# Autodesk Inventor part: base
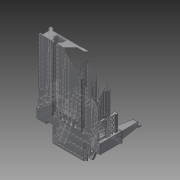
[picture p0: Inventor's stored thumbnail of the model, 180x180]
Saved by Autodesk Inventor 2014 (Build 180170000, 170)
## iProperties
Created: 2013-07
Part Number: base
Material: Generic
Document SubType Name: Modeling
Designer: Brent J. Rosenburgh
Density: 1 g/cm^3
Appearance: Default
Author: Brent J. Rosenburgh
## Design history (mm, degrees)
sketch "Sketch1"
  geometry: L1 (-56, -78)-(56, -78); L2 (56, -78)-(56, -100); L3 (56, -100)-(-56, -100); L4 (-56, -100)-(-56, -78); 1 further point
  constraints: 8 end point, 2 parallel, 1 horizontal, 1 perpendicular
extrude "Extrusion1" new body sketch "Sketch1" distance "d0" = 136; taper "d1" = 0 deg
sketch "Sketch2"
  geometry: L1 (0, 136)-(12, 136); L2 (12, 136)-(12, 124); L3 (12, 124)-(0, 124); L4 (0, 124)-(0, 136); L5 (112, 136)-(100, 136); L6 (100, 136)-(100, 124); L7 (100, 124)-(112, 124); L8 (112, 124)-(112, 136); 1 further point
  constraints: 16 end point, 4 parallel, 2 horizontal, 2 perpendicular
extrude "Extrusion2" join sketch "Sketch2" distance "d2" = 16; taper "d3" = 0 deg
sketch "Sketch3"
  geometry: L1 (0, 136)-(0, 124) reference; L2 (0, 124)-(12, 124) reference; L3 (12, 124)-(12, 136) reference; L4 (12, 136)-(0, 136) reference; L5 (15, 121)-(-3, 121); L6 (-3, 121)-(-3, 139); L7 (-3, 139)-(15, 139); L8 (15, 139)-(15, 121); 1 further point
  constraints: 8 end point, 2 parallel, 1 horizontal, 1 perpendicular
extrude "Extrusion3" join sketch "Sketch3" distance "d4" = 38; taper "d5" = 0 deg
sketch "Sketch4"
  geometry: L1 (112, 136)-(100, 136) reference; L2 (100, 136)-(100, 124) reference; L3 (100, 124)-(112, 124) reference; L4 (112, 124)-(112, 136) reference; L5 (115, 121)-(97, 121); L6 (97, 121)-(97, 139); L7 (97, 139)-(115, 139); L8 (115, 139)-(115, 121); 1 further point
  constraints: 8 end point, 2 parallel, 1 horizontal, 1 perpendicular
extrude "Extrusion4" join sketch "Sketch4" distance "d6" = 38; taper "d7" = 0 deg
sketch "Sketch5"
  geometry: L1 (15, 121)-(-3, 121) reference; L2 (15, 139)-(15, 121) reference; L3 (-3, 139)-(15, 139) reference; L4 (-3, 121)-(-3, 139) reference; 1 further point
extrude "Extrusion5" join sketch "Sketch5" distance "d8" = 1; taper "d9" = 45 deg
sketch "Sketch6"
  geometry: L1 (-4, 120)-(-4, 140) reference; L2 (16, 120)-(-4, 120) reference; L3 (16, 140)-(16, 120) reference; L4 (-4, 140)-(16, 140) reference; 1 further point
extrude "Extrusion6" join sketch "Sketch6" distance "d10" = 1; taper "d11" = 0 deg
sketch "Sketch7"
  geometry: L1 (-4, 140)-(-4, 120) reference; L2 (-4, 120)-(16, 120) reference; L3 (16, 120)-(16, 140) reference; L4 (16, 140)-(-4, 140) reference; 1 further point
extrude "Extrusion7" join sketch "Sketch7" distance "d12" = 1; taper "d13" = -45 deg
sketch "Sketch8"
  geometry: L1 (115, 121)-(97, 121) reference; L2 (115, 139)-(115, 121) reference; L3 (97, 139)-(115, 139) reference; L4 (97, 121)-(97, 139) reference; 1 further point
extrude "Extrusion8" join sketch "Sketch8" distance "d14" = 1; taper "d15" = 45 deg
sketch "Sketch9"
  geometry: L1 (96, 120)-(96, 140) reference; L2 (116, 120)-(96, 120) reference; L3 (116, 140)-(116, 120) reference; L4 (96, 140)-(116, 140) reference; 1 further point
extrude "Extrusion9" join sketch "Sketch9" distance "d16" = 1; taper "d17" = 0 deg
sketch "Sketch10"
  geometry: L1 (96, 140)-(96, 120) reference; L2 (96, 120)-(116, 120) reference; L3 (116, 120)-(116, 140) reference; L4 (116, 140)-(96, 140) reference; 1 further point
extrude "Extrusion10" join sketch "Sketch10" distance "d18" = 1; taper "d19" = -45 deg
sketch "Sketch11"
  geometry: L1 (113, 137)-(99, 137); L2 (99, 137)-(99, 123); L3 (99, 123)-(113, 123); L4 (113, 123)-(113, 137); L5 (113, 137)-(99, 123); L6 (99, 137)-(113, 123); 2 further points
  constraints: 12 end point, 2 midpoint, 2 parallel, 1 horizontal, 1 perpendicular
extrude "Extrusion11" join sketch "Sketch11" distance "d20" = 34; taper "d21" = -5 deg
sketch "Sketch12"
  geometry: L1 (-1, 123)-(13, 123); L2 (13, 123)-(13, 137); L3 (13, 137)-(-1, 137); L4 (-1, 137)-(-1, 123); L5 (-1, 123)-(13, 137); L6 (13, 123)-(-1, 137); 2 further points
  constraints: 12 end point, 2 midpoint, 2 parallel, 1 horizontal, 1 perpendicular
extrude "Extrusion12" join sketch "Sketch12" distance "d22" = 34; taper "d23" = -5 deg
sketch "Sketch13"
  geometry: L1 (110.025, 134.025)-(110.025, 125.975) reference; L2 (101.975, 134.025)-(110.025, 134.025) reference; L3 (101.975, 125.975)-(101.975, 134.025) reference; L4 (110.025, 125.975)-(101.975, 125.975) reference; 1 further point
extrude "Extrusion13" join sketch "Sketch13" distance "d24" = 1; taper "d25" = 45 deg
sketch "Sketch14"
  geometry: L1 (1.975, 125.975)-(1.975, 134.025) reference; L2 (10.025, 125.975)-(1.975, 125.975) reference; L3 (10.025, 134.025)-(10.025, 125.975) reference; L4 (1.975, 134.025)-(10.025, 134.025) reference; 1 further point
extrude "Extrusion14" join sketch "Sketch14" distance "d26" = 1; taper "d27" = 45 deg
sketch "Sketch15"
  geometry: L1 (111.025, 124.975)-(100.975, 124.975) reference; L2 (111.025, 135.025)-(111.025, 124.975) reference; L3 (100.975, 135.025)-(111.025, 135.025) reference; L4 (100.975, 124.975)-(100.975, 135.025) reference; 1 further point
extrude "Extrusion15" join sketch "Sketch15" distance "d28" = 4.5; taper "d29" = 0 deg
sketch "Sketch16"
  geometry: L1 (0.975, 135.025)-(11.025, 135.025) reference; L2 (0.975, 124.975)-(0.975, 135.025) reference; L3 (11.025, 124.975)-(0.975, 124.975) reference; L4 (11.025, 135.025)-(11.025, 124.975) reference; 1 further point
extrude "Extrusion16" join sketch "Sketch16" distance "d30" = 4.5; taper "d31" = 0 deg
sketch "Sketch17"
  geometry: L1 (-10.051, 4.5)-(0, 4.5) reference; L2 (-10.051, 0)-(-10.051, 4.5) reference; L3 (-2.826, 4.5)-(-2.826, -0.41); L4 (-2.826, -0.41)-(-6.702, -0.41); L5 (-6.702, -0.41)-(-10.051, -1.07); L6 (-10.051, -1.07)-(-10.051, 0); 1 further point
  constraints: 8 end point, 2 parallel, 1 perpendicular, 1 point on line
extrude "Extrusion17" cut sketch "Sketch17" distance "d32" = 115.75; taper "d33" = 0 deg
sketch "Sketch18"
  geometry: L1 (0, 14)-(5.994, 14); L2 (5.994, 14)-(5.994, 10); L3 (5.994, 10)-(0, 10); L4 (0, 10)-(0, 14); 1 further point
  constraints: 8 end point, 2 parallel, 1 horizontal, 1 perpendicular
extrude "Extrusion18" join sketch "Sketch18" distance "d34" = 29.25; taper "d35" = 0 deg
sketch "Sketch19"
  geometry: L1 (14.949, 13.961)-(8.949, 13.961); L2 (8.949, 13.961)-(8.949, 9.961); L3 (8.949, 9.961)-(14.949, 9.961); L4 (14.949, 9.961)-(14.949, 13.961); 1 further point
  constraints: 8 end point, 2 parallel, 1 horizontal, 1 perpendicular
extrude "Extrusion19" join sketch "Sketch19" distance "d36" = 29.25; taper "d37" = 0 deg
sketch "Sketch20"
  geometry: L1 (0, 29.25)-(6, 29.25) reference; L2 (5, 3)-(1, 3); L3 (1, 3)-(1, 8); L4 (1, 8)-(5, 8); L5 (5, 8)-(5, 3); L6 (5, 11)-(1, 11); L7 (1, 11)-(1, 16); L8 (1, 16)-(5, 16); L9 (5, 16)-(5, 11); L10 (5, 19)-(1, 19); L11 (1, 19)-(1, 24); L12 (1, 24)-(5, 24); L13 (5, 24)-(5, 19); L14 (1, 27)-(5, 27); L15 (5, 27)-(5, 29.25); L16 (5, 29.25)-(1, 29.25); L17 (1, 29.25)-(1, 27); 1 further point
  constraints: 32 end point, 8 parallel, 4 horizontal, 4 perpendicular, 2 point on line
extrude "Extrusion20" join sketch "Sketch20" distance "d38" = 10.25; taper "d39" = 0 deg
sketch "Sketch21"
  geometry: L1 (0, 29.25)-(5.994, 29.25) reference; L2 (5, 3)-(1, 3); L3 (1, 3)-(1, 8); L4 (1, 8)-(5, 8); L5 (5, 8)-(5, 3); L6 (1, 11)-(5, 11); L7 (5, 11)-(5, 16); L8 (5, 16)-(1, 16); L9 (1, 16)-(1, 11); L10 (5, 19)-(1, 19); L11 (1, 19)-(1, 24); L12 (1, 24)-(5, 24); L13 (5, 24)-(5, 19); L14 (1, 27)-(5, 27); L15 (5, 27)-(5, 29.25); L16 (5, 29.25)-(1, 29.25); L17 (1, 29.25)-(1, 27); 1 further point
  constraints: 32 end point, 8 parallel, 4 horizontal, 4 perpendicular, 1 point on line
extrude "Extrusion21" join sketch "Sketch21" distance "d40" = 10.25; taper "d41" = 0 deg
sketch "Sketch22"
  geometry: L1 (5, 5)-(1, 5); L2 (1, 5)-(1, 6); L3 (1, 6)-(5, 6); L4 (5, 6)-(5, 5); 1 further point
  constraints: 8 end point, 2 parallel, 1 horizontal, 1 perpendicular
extrude "Extrusion22" join sketch "Sketch22" distance "d42" = 28; taper "d43" = 0 deg
sketch "Sketch23"
  geometry: L1 (4, 0)-(4, -9.961) reference; L2 (0, 0)-(0, -9.961) reference; L3 (4, -4.981)-(0, -4.981); L4 (0, -4.981)-(0, -4); L5 (0, -4)-(4, -4); L6 (4, -4)-(4, -4.981); 1 further point
  constraints: 8 end point, 2 parallel, 1 horizontal, 1 midpoint, 1 perpendicular, 1 point on line
extrude "Extrusion23" join sketch "Sketch23" distance "d44" = 28; taper "d45" = 0 deg
sketch "Sketch24"
  geometry: L1 (-13, 36)-(0, 36); L2 (0, 36)-(0, 32); L3 (0, 32)-(-13, 32); L4 (-13, 32)-(-13, 36); 1 further point
  constraints: 8 end point, 2 parallel, 1 horizontal, 1 perpendicular
extrude "Extrusion24" join sketch "Sketch24" distance "d46" = 19; taper "d47" = 0 deg
sketch "Sketch25"
  geometry: L1 (13, 36)-(0, 36); L2 (0, 36)-(0, 32); L3 (0, 32)-(13, 32); L4 (13, 32)-(13, 36); 1 further point
  constraints: 8 end point, 2 parallel, 1 horizontal, 1 perpendicular
extrude "Extrusion25" join sketch "Sketch25" distance "d48" = 19; taper "d49" = 0 deg
sketch "Sketch26"
  geometry: L1 (0, 36)-(0, 32) reference; L2 (13, 32)-(13, 36) reference; L3 (0, 36)-(-32, 17); L4 (0, 32)-(-32, 13); L5 (-32, 13)-(-32, 17); 1 further point
  constraints: 6 end point, 2 parallel
extrude "Extrusion26" join sketch "Sketch26" distance "d50" = 9; taper "d51" = 0 deg
sketch "Sketch27"
  geometry: L1 (0, 32)-(0, 36) reference; L2 (0, 36)-(32, 17); L3 (32, 17)-(32, 13); L4 (32, 13)-(0, 32); 1 further point
  constraints: 6 end point, 2 parallel
extrude "Extrusion27" join sketch "Sketch27" distance "d52" = 9; taper "d53" = 0 deg
sketch "Sketch28"
  geometry: L1 (-41, -100)-(41, -100) reference; L2 (29, -100)-(-29, -100); L3 (-29, -100)-(-29, -94.5); L4 (-29, -94.5)-(29, -94.5); L5 (29, -94.5)-(29, -100); 1 further point
  constraints: 8 end point, 2 parallel, 1 horizontal, 1 perpendicular, 1 point on line
  dimensions: "d54" = 5.5 distance of L2.end L3.end
extrude "Extrusion28" join sketch "Sketch28" distance "d55" = 28; taper "d56" = 0 deg
sketch "Sketch29"
  geometry: L1 (29, -94.5)-(-29, -94.5); L2 (-29, -94.5)-(-29, -89); L3 (-29, -89)-(29, -89); L4 (29, -89)-(29, -94.5); 1 further point
  constraints: 8 end point, 2 parallel, 1 horizontal, 1 perpendicular
extrude "Extrusion29" join sketch "Sketch29" distance "d57" = 19; taper "d58" = 0 deg
sketch "Sketch30"
  geometry: L1 (29, -89)-(-29, -89); L2 (-29, -89)-(-29, -83.5); L3 (-29, -83.5)-(29, -83.5); L4 (29, -83.5)-(29, -89); 1 further point
  constraints: 8 end point, 2 parallel, 1 horizontal, 1 perpendicular
  dimensions: "d59" = 5.5 distance of L1.end L2.end
extrude "Extrusion30" join sketch "Sketch30" distance "d60" = 10; taper "d61" = 0 deg
sketch "Sketch32"
  geometry: L1 (-17, 11)-(-12, 11); L2 (-12, 11)-(-12, 2); L3 (-12, 2)-(-17, 2); L4 (-17, 2)-(-17, 11); L5 (-7, 11)-(-2, 11); L6 (-2, 11)-(-2, 2); L7 (-2, 2)-(-7, 2); L8 (-7, 2)-(-7, 11); 1 further point
  constraints: 16 end point, 4 parallel, 2 horizontal, 2 perpendicular
extrude "Extrusion32" join sketch "Sketch32" distance "d64" = 10.75; taper "d65" = 0 deg
sketch "Sketch33"
  geometry: L1 (17, 11)-(12, 11); L2 (12, 11)-(12, 2); L3 (12, 2)-(17, 2); L4 (17, 2)-(17, 11); L5 (2, 11)-(7, 11); L6 (7, 11)-(7, 2); L7 (7, 2)-(2, 2); L8 (2, 2)-(2, 11); 1 further point
  constraints: 16 end point, 4 parallel, 2 horizontal, 2 perpendicular
extrude "Extrusion33" join sketch "Sketch33" distance "d66" = 10.75; taper "d67" = 0 deg
sketch "Sketch34"
  geometry: L1 (58, 0)-(58, 10) reference; L2 (58, 8)-(53, 8); L3 (53, 8)-(53, 2); L4 (53, 2)-(58, 2); L5 (58, 2)-(58, 8); 1 further point
  constraints: 8 end point, 2 parallel, 1 horizontal, 1 perpendicular, 1 point on line
extrude "Extrusion34" join sketch "Sketch34" distance "d68" = 14.5; taper "d69" = 0 deg
sketch "Sketch35"
  geometry: L1 (0, 0)-(0, 10) reference; L2 (0, 8)-(5, 8); L3 (5, 8)-(5, 2); L4 (5, 2)-(0, 2); L5 (0, 2)-(0, 8); 1 further point
  constraints: 8 end point, 2 parallel, 1 horizontal, 1 perpendicular, 1 point on line
extrude "Extrusion35" join sketch "Sketch35" distance "d70" = 14.5; taper "d71" = 0 deg
sketch "Sketch36"
  geometry: L1 (58, -9)-(58, 0) reference; L2 (0, -9)-(0, 0) reference; L3 (0, -7)-(5, -7); L4 (5, -7)-(5, -2); L5 (5, -2)-(0, -2); L6 (0, -2)-(0, -7); L7 (58, -2)-(53, -2); L8 (53, -2)-(53, -7); L9 (53, -7)-(58, -7); L10 (58, -7)-(58, -2); 1 further point
  constraints: 16 end point, 4 parallel, 2 horizontal, 2 perpendicular, 2 point on line
extrude "Extrusion36" join sketch "Sketch36" distance "d72" = 14.5; taper "d73" = 0 deg
sketch "Sketch37"
  geometry: L1 (58, -9)-(58, 0) reference; L2 (0, -9)-(0, 0) reference; L3 (0, -7)-(5, -7); L4 (5, -7)-(5, -2); L5 (5, -2)-(0, -2); L6 (0, -2)-(0, -7); L7 (58, -2)-(53, -2); L8 (53, -2)-(53, -7); L9 (53, -7)-(58, -7); L10 (58, -7)-(58, -2); 1 further point
  constraints: 16 end point, 4 parallel, 2 horizontal, 2 perpendicular, 2 point on line
extrude "Extrusion37" join sketch "Sketch37" distance "d74" = 14.5; taper "d75" = 0 deg
sketch "Sketch38"
  geometry: L1 (-28, 0)-(-28, 16.5) reference; L2 (-18, 16.5)-(-28, 16.5); L3 (-28, 16.5)-(-28, 15); L4 (-28, 15)-(-18, 15); L5 (-18, 15)-(-18, 16.5); L6 (-9, 11)-(-19, 11); L7 (-19, 11)-(-19, 9.5); L8 (-19, 9.5)-(-9, 9.5); L9 (-9, 9.5)-(-9, 11); L10 (0, 5.5)-(-10, 5.5); L11 (-10, 5.5)-(-10, 4); L12 (-10, 4)-(0, 4); L13 (0, 4)-(0, 5.5); 1 further point
  constraints: 24 end point, 6 parallel, 3 horizontal, 3 perpendicular, 1 point on line
  dimensions: "d76" = 1.5 distance of L7.end L6.end
extrude "Extrusion38" join sketch "Sketch38" distance "d77" = 2; taper "d78" = 0 deg
sketch "Sketch39"
  geometry: L1 (18, 16.5)-(28, 16.5); L2 (28, 16.5)-(28, 15); L3 (28, 15)-(18, 15); L4 (18, 15)-(18, 16.5); L5 (9, 11)-(19, 11); L6 (19, 11)-(19, 9.5); L7 (19, 9.5)-(9, 9.5); L8 (9, 9.5)-(9, 11); L9 (0, 5.5)-(10, 5.5); L10 (10, 5.5)-(10, 4); L11 (10, 4)-(0, 4); L12 (0, 4)-(0, 5.5); 1 further point
  constraints: 24 end point, 6 parallel, 3 horizontal, 3 perpendicular
  dimensions: "d79" = 1.5 distance of L5.end L6.end
extrude "Extrusion39" join sketch "Sketch39" distance "d80" = 2; taper "d81" = 0 deg
sketch "Sketch40"
  geometry: L1 (31, -83.5)-(-31, -83.5); L2 (-31, -83.5)-(-31, -85); L3 (-31, -85)-(31, -85); L4 (31, -85)-(31, -83.5); 1 further point
  constraints: 8 end point, 2 parallel, 1 horizontal, 1 perpendicular
extrude "Extrusion40" join sketch "Sketch40" distance "d82" = 1; taper "d83" = 0 deg
sketch "Sketch41"
  geometry: L1 (29, -94.5)-(29, -90.5) reference; L2 (29, -90.5)-(31, -90.5) reference; L3 (31, -89)-(31, -90.5) reference; L4 (-31, -89)-(31, -89) reference; L5 (-31, -90.5)-(-31, -89) reference; L6 (-29, -90.5)-(-31, -90.5) reference; L7 (-29, -90.5)-(29, -90.5); 1 further point
  constraints: 2 end point, 1 perpendicular
extrude "Extrusion41" join sketch "Sketch41" distance "d84" = 1; taper "d85" = 0 deg
sketch "Sketch42"
  geometry: L1 (29, -96)-(31, -96) reference; L2 (31, -94.5)-(31, -96) reference; L3 (-31, -94.5)-(31, -94.5) reference; L4 (-31, -96)-(-31, -94.5) reference; L5 (-29, -96)-(-31, -96) reference; L6 (-29, -100)-(29, -100) reference; L7 (-29, -96)-(29, -96); 1 further point
  constraints: 2 end point, 1 parallel
extrude "Extrusion42" join sketch "Sketch42" distance "d86" = 1; taper "d87" = 0 deg
sketch "Sketch43"
  geometry: L1 (41, -78)-(-41, -78) reference; L2 (-31, -78)-(31, -78); L3 (31, -78)-(31, -79.5); L4 (31, -79.5)-(-31, -79.5); L5 (-31, -79.5)-(-31, -78); 1 further point
  constraints: 8 end point, 2 parallel, 1 horizontal, 1 perpendicular, 1 point on line
  dimensions: "d88" = 1.5 distance of L2.end L3.end
extrude "Extrusion43" join sketch "Sketch43" distance "d89" = 1; taper "d90" = 0 deg
sketch "Sketch44"
  geometry: L1 (-56, -100)-(-56, -78) reference; L2 (56, -78)-(56, -100) reference; L3 (-56, -97)-(-51, -97); L4 (-51, -97)-(-51, -86); L5 (-51, -86)-(-56, -81); L6 (56, -97)-(51, -97); L7 (51, -97)-(51, -86); L8 (51, -86)-(56, -81); 1 further point
  constraints: 12 end point, 4 perpendicular, 4 point on line, 1 parallel
extrude "Extrusion44" cut sketch "Sketch44" distance "d91" = 91.5; taper "d92" = 0 deg
sketch "Sketch45"
  geometry: L1 (56, -100)-(-56, -100) reference; L2 (-56, -81)-(-51, -86) reference; L3 (-51, -86)-(-51, -97) reference; L4 (-29, -100)-(-29, -97); L5 (-29, -97)-(-34.5, -91.5); L6 (-34.5, -91.5)-(-34.5, -86); L7 (-25, -100)-(-25, -97); L8 (-25, -97)-(-19.5, -91.5); L9 (-19.5, -91.5)-(-19.5, -86); L10 (-19.5, -86)-(-34.5, -86); L11 (29, -100)-(29, -97); L12 (29, -97)-(34.5, -91.5); L13 (34.5, -91.5)-(34.5, -86); L14 (25, -100)-(25, -97); L15 (25, -97)-(19.5, -91.5); L16 (19.5, -91.5)-(19.5, -86); L17 (19.5, -86)-(34.5, -86); 1 further point
  constraints: 28 end point, 9 parallel, 5 perpendicular, 4 point on line
extrude "Extrusion45" cut sketch "Sketch45" distance "d93" = 120.5; taper "d94" = 0 deg
sketch "Sketch46"
  geometry: L1 (34.288, 91.75)-(77.796, 91.75); L2 (77.796, 91.75)-(77.796, 88); L3 (77.796, 88)-(34.288, 88); L4 (34.288, 88)-(34.288, 91.75); 1 further point
  constraints: 8 end point, 2 parallel, 1 horizontal, 1 perpendicular
extrude "Extrusion46" join sketch "Sketch46" distance "d95" = 14; taper "d96" = 0 deg
sketch "Sketch47"
  geometry: L1 (43.507, 0)-(43.507, 14) reference; L2 (0, 14)-(43.507, 14); L3 (43.507, 14)-(43.507, 10); L4 (43.507, 10)-(0, 10); L5 (0, 10)-(0, 14); 1 further point
  constraints: 8 end point, 2 parallel, 1 horizontal, 1 perpendicular, 1 point on line
extrude "Extrusion47" join sketch "Sketch47" distance "d97" = 1; taper "d98" = 0 deg
sketch "Sketch48"
  geometry: L1 (6.48, 10)-(7, 10); L2 (7, 10)-(7, 0); L3 (7, 0)-(6.48, 0); L4 (6.48, 0)-(6.48, 10); L5 (36.48, 10)-(37, 10); L6 (37, 10)-(37, 0); L7 (37, 0)-(36.48, 0); L8 (36.48, 0)-(36.48, 10); L9 (29, 10)-(29.52, 10); L10 (29.52, 10)-(29.52, 0); L11 (29.52, 0)-(29, 0); L12 (29, 0)-(29, 10); L13 (13.834, 10)-(14.354, 10); L14 (14.354, 10)-(14.354, 0); L15 (14.354, 0)-(13.834, 0); L16 (13.834, 0)-(13.834, 10); L17 (21.234, 10)-(21.754, 10); L18 (21.754, 10)-(21.754, 0); L19 (21.754, 0)-(21.234, 0); L20 (21.234, 0)-(21.234, 10); 1 further point
  constraints: 40 end point, 10 parallel, 5 horizontal, 5 perpendicular
extrude "Extrusion48" cut sketch "Sketch48" distance "d99" = 0.5; taper "d100" = 0 deg
sketch "Sketch49"
  geometry: L1 (-56, -78)-(56, -78) reference; L2 (-19.5, -86)-(-19.5, -91.5) reference; L3 (-19.5, -91.5)-(-25, -97) reference; L4 (-51, -78)-(-46, -83); L5 (51, -78)-(46, -83); L6 (46, -83)-(-46, -83); 1 further point
  constraints: 6 end point, 3 perpendicular, 2 point on line
extrude "Extrusion49" cut sketch "Sketch49" distance "d101" = 4.25; taper "d102" = 0 deg
sketch "Sketch50"
  geometry: L1 (77.796, -33)-(34.288, -33) reference; L2 (41.316, -110)-(70.796, -110); L3 (70.796, -110)-(70.796, -33); L4 (70.796, -33)-(41.316, -33); L5 (41.316, -33)-(41.316, -110); L6 (95, -33)-(106.949, -33); L7 (106.949, -33)-(106.949, -110); L8 (106.949, -110)-(95, -110); L9 (95, -110)-(95, -33); L10 (17, -110)-(5, -110); L11 (5, -110)-(5, -33); L12 (5, -33)-(17, -33); L13 (17, -33)-(17, -110); 1 further point
  constraints: 24 end point, 6 parallel, 3 horizontal, 3 perpendicular, 3 point on line
extrude "Extrusion50" cut sketch "Sketch50" distance "d103" = 5; taper "d104" = 0 deg
sketch "Sketch51"
  geometry: L1 (41.316, -33)-(70.796, -33) reference; L2 (41.316, -110)-(41.316, -33) reference; L3 (70.796, -110)-(41.316, -110) reference; L4 (70.796, -33)-(70.796, -110) reference; 1 further point
extrude "Extrusion51" cut sketch "Sketch51" distance "d105" = 13.25; taper "d106" = 0 deg
sketch "Sketch52"
  geometry: L1 (17, -110)-(5, -110) reference; L2 (17, -33)-(17, -110) reference; L3 (5, -33)-(17, -33) reference; L4 (11, -33)-(11, -110); 1 further point
  constraints: 2 end point, 2 midpoint
extrude "Extrusion52" cut sketch "Sketch52" distance "d107" = 13.25; taper "d108" = 0 deg
sketch "Sketch53"
  geometry: L1 (95, -33)-(106.949, -33) reference; L2 (95, -110)-(95, -33) reference; L3 (106.949, -110)-(95, -110) reference; L4 (100.975, -33)-(100.975, -110); 1 further point
  constraints: 2 end point, 2 midpoint
extrude "Extrusion53" cut sketch "Sketch53" distance "d109" = 13.25; taper "d110" = 0 deg
chamfer "Chamfer1" distance "d111" = 5.97; stored, may be unused: second distance "d112" = 2, angle "d113" = 45 deg
sketch "Sketch54"
  geometry: L1 (70.796, -33)-(70.796, -110) reference; L2 (41.316, -110)-(41.316, -33) reference; L3 (41.316, -33)-(34.288, -33) reference; L4 (77.796, -33)-(70.796, -33) reference; L5 (95, -110)-(95, -33) reference; L6 (17, -33)-(17, -110) reference; L7 (5, -33)-(17, -33) reference; L8 (17, -33)-(34.288, -33); L9 (77.796, -33)-(95, -33); L10 (17, -110)-(41.316, -110); L11 (70.796, -110)-(95, -110); 1 further point
  constraints: 8 end point, 3 collinear, 1 parallel
extrude "Extrusion54" cut sketch "Sketch54" distance "d114" = 5; taper "d115" = 0 deg
sketch "Sketch55"
  geometry: L1 (95, -33)-(100.975, -33) reference; L2 (95, -33)-(95, -5); L3 (95, -5)-(114, -5); L4 (114, -5)-(114, -14); L5 (114, -14)-(100.975, -14); L6 (100.975, -14)-(100.975, -33); 1 further point
  constraints: 10 end point, 3 perpendicular, 2 parallel
sketch "Sketch56"
  geometry: L1 (41.316, -33)-(70.796, -33) reference; L2 (70.796, -33)-(70.796, -110) reference; L3 (70.796, -33)-(70.796, -14); L4 (41.316, -33)-(41.316, -14); L5 (70.796, -110)-(41.316, -110) reference; L6 (41.316, -14)-(41.316, -0.595); L7 (41.316, -0.595)-(70.796, -0.595); L8 (70.796, -0.595)-(70.796, -14); 1 further point
  constraints: 10 end point, 2 perpendicular, 1 collinear, 1 parallel
sketch "Sketch57"
  geometry: L1 (11, -33)-(17, -33) reference; L2 (17, -110)-(11, -110) reference; L3 (17, -33)-(17, -5); L4 (17, -5)-(-3, -5); L5 (-3, -5)-(-3, -14); L6 (-3, -14)-(11, -14); L7 (11, -14)-(11, -33); 1 further point
  constraints: 10 end point, 3 parallel, 2 perpendicular
extrude "Extrusion55" cut sketch "Sketch57" distance "d116" = 10.25; taper "d117" = 0 deg
extrude "Extrusion56" cut sketch "Sketch55" distance "d118" = 10.25; taper "d119" = 0 deg
extrude "Extrusion57" cut sketch "Sketch56" distance "d120" = 10.25; taper "d121" = 0 deg
sketch "Sketch58"
  geometry: L1 (70.796, -0.595)-(70.796, -110) reference; L2 (41.316, -0.595)-(70.796, -0.595) reference; L3 (41.316, -0.595)-(70.796, -0.595); L4 (70.796, -0.595)-(70.796, -14); L5 (70.796, -14)-(41.316, -14); L6 (41.316, -14)-(41.316, -0.595); 1 further point
  constraints: 8 end point, 2 parallel, 1 horizontal, 1 perpendicular, 1 point on line
extrude "Extrusion58" cut sketch "Sketch58" distance "d122" = 5.5; taper "d123" = 0 deg
fillet "Fillet1" dims "d124" = 12.25
fillet "Fillet2" dims "d125" = 8
chamfer "Chamfer2" distance "d126" = 13.22; stored, may be unused: second distance "d127" = 2, angle "d128" = 45 deg
chamfer "Chamfer3" distance "d129" = 2.22; stored, may be unused: second distance "d130" = 2, angle "d131" = 45 deg
chamfer "Chamfer4" distance "d132" = 93.72; stored, may be unused: second distance "d133" = 4, angle "d134" = 45 deg
chamfer "Chamfer5" distance "d135" = 95.97; stored, may be unused: second distance "d136" = 4, angle "d137" = 45 deg
chamfer "Chamfer6" distance "d138" = 95.97; stored, may be unused: second distance "d139" = 4, angle "d140" = 45 deg
sketch "Sketch59"
  geometry: L1 (70.796, 13.815)-(41.316, 13.815) reference; L2 (41.316, 33)-(70.796, 33) reference; L3 (55, 33)-(57, 33); L4 (57, 33)-(57, 13.815); L5 (57, 13.815)-(55, 13.815); L6 (55, 13.815)-(55, 33); L7 (63, 13.815)-(65, 13.815); L8 (65, 13.815)-(65, 33); L9 (65, 33)-(63, 33); L10 (63, 33)-(63, 13.815); L11 (49, 33)-(47, 33); L12 (47, 33)-(47, 13.815); L13 (47, 13.815)-(49, 13.815); L14 (49, 13.815)-(49, 33); 1 further point
  constraints: 24 end point, 6 parallel, 4 point on line, 3 horizontal, 3 perpendicular
extrude "Extrusion59" join sketch "Sketch59" distance "d141" = 14; taper "d142" = 0 deg
sketch "Sketch60"
  geometry: L1 (73.796, 18.595)-(44.316, 18.595) reference; L2 (50, 31.815)-(52, 31.815); L3 (52, 31.815)-(52, 18.595); L4 (52, 18.595)-(50, 18.595); L5 (50, 18.595)-(50, 31.815); L6 (58, 31.815)-(60, 31.815); L7 (60, 31.815)-(60, 18.595); L8 (60, 18.595)-(58, 18.595); L9 (58, 18.595)-(58, 31.815); L10 (66, 31.815)-(68, 31.815); L11 (68, 31.815)-(68, 18.595); L12 (68, 18.595)-(66, 18.595); L13 (66, 18.595)-(66, 31.815); 1 further point
  constraints: 24 end point, 6 parallel, 3 horizontal, 3 perpendicular, 3 point on line
extrude "Extrusion60" join sketch "Sketch60" distance "d143" = 14.75; taper "d144" = 0 deg
chamfer "Chamfer7" distance "d145" = 2.47; stored, may be unused: second distance "d146" = 4, angle "d147" = 45 deg
chamfer "Chamfer8" distance "d148" = 3; stored, may be unused: second distance "d149" = 4, angle "d150" = 45 deg
sketch "Sketch61"
  geometry: L1 (13, 36)-(0, 36) reference; L2 (0, 36)-(-32, 17) reference; L3 (-32, 17)-(-32, 13) reference; L4 (-32, 13)-(0, 32) reference; L5 (13, 32)-(13, 36) reference; L6 (-32, 14)-(0, 33); L7 (0, 33)-(13, 33); 1 further point
  constraints: 4 end point, 2 point on line, 1 parallel, 1 perpendicular
extrude "Extrusion61" join sketch "Sketch61" distance "d151" = 0.5; taper "d152" = 0 deg
sketch "Sketch62"
  geometry: L1 (0, 36)-(-13, 36) reference; L2 (-13, 36)-(-13, 32) reference; L3 (32, 13)-(32, 17) reference; L4 (32, 17)-(0, 36) reference; L5 (32, 14)-(0, 33); L6 (0, 33)-(-13, 33); 1 further point
  constraints: 4 end point, 2 point on line, 1 parallel, 1 perpendicular
extrude "Extrusion62" join sketch "Sketch62" distance "d153" = 0.5; taper "d154" = 0 deg
sketch "Sketch63"
  geometry: L1 (32, 17)-(0, 36) reference; L2 (0, 32)-(0, 36) reference; L3 (0, 32)-(32, 13) reference; L4 (32, 13)-(32, 17) reference; L5 (32, 14)-(0, 33); 1 further point
  constraints: 2 end point, 2 point on line, 1 parallel
extrude "Extrusion63" join sketch "Sketch63" distance "d155" = 0.5; taper "d156" = 0 deg
sketch "Sketch64"
  geometry: L1 (0, 36)-(0, 32) reference; L2 (0, 36)-(-32, 17) reference; L3 (-32, 17)-(-32, 13) reference; L4 (-32, 13)-(0, 32) reference; L5 (-32, 14)-(0, 33); 1 further point
  constraints: 2 end point, 2 point on line, 1 parallel
extrude "Extrusion64" join sketch "Sketch64" distance "d157" = 0.5; taper "d158" = 0 deg
sketch "Sketch65"
  geometry: L1 (-9.5, 4)-(-9.5, 1) reference; L2 (0, 4)-(0, 0) reference; L3 (0, 4)-(-9.5, 4) reference; L4 (-9.5, 1)-(0, 1); 1 further point
  constraints: 2 end point, 1 parallel, 1 point on line
extrude "Extrusion65" join sketch "Sketch65" distance "d159" = 0.5; taper "d160" = 0 deg
sketch "Sketch66"
  geometry: L1 (9.5, 1)-(9.5, 4) reference; L2 (0, 4)-(9.5, 4) reference; L3 (0, 0)-(0, 4) reference; L4 (10, 1)-(9.5, 1) reference; L5 (9.5, 1)-(0, 1); 1 further point
  constraints: 2 end point, 1 collinear, 1 point on line
extrude "Extrusion66" join sketch "Sketch66" distance "d161" = 0.5; taper "d162" = 0 deg
sketch "Sketch67"
  geometry: L1 (0, 0)-(0, 1) reference; L2 (9, 0)-(0, 0) reference; L3 (9, 1)-(9, 0) reference; L4 (9.5, 4)-(9.5, 1) reference; L5 (0, 1)-(9, 1); 1 further point
  constraints: 2 end point, 1 perpendicular
extrude "Extrusion67" cut sketch "Sketch67" distance "d163" = 0.5; taper "d164" = 0 deg
sketch "Sketch68"
  geometry: L1 (0, 0)-(0, 1) reference; L2 (0, 0)-(9, 0) reference; L3 (9, 1)-(9, 0) reference; L4 (0, 1)-(-0.5, 1) reference; L5 (0, 1)-(9, 1); 1 further point
  constraints: 2 end point, 1 collinear
extrude "Extrusion68" cut sketch "Sketch68" distance "d165" = 0.5; taper "d166" = 0 deg
sketch "Sketch69"
  geometry: L1 (-41, -78)-(-41, -100) reference; L2 (-41, -100)-(-29, -100) reference; L3 (-29, -100)-(-29, -85) reference; L4 (-29, -85)-(-31, -85) reference; L5 (31, -85)-(29, -85) reference; L6 (29, -85)-(29, -100) reference; L7 (29, -100)-(41, -100) reference; L8 (41, -100)-(41, -78) reference; L9 (41, -78)-(31, -78) reference; L10 (-31, -85)-(-41, -85); L11 (31, -85)-(41, -85); 1 further point
  constraints: 4 end point, 2 equal length, 2 point on line
extrude "Extrusion69" cut sketch "Sketch69" distance "d167" = 2; taper "d168" = 0 deg
sketch "Sketch70"
  geometry: L1 (29.5, 3)-(29.5, 19) reference; L2 (0, 22)-(0, 0) reference; L3 (121, 0)-(0, 0) reference; L4 (121, 0)-(121, 3) reference; L5 (0, 15)-(29.5, 15); L6 (29.5, 3)-(29.5, 0); L7 (4, 15)-(4, 0); L8 (15, 15)-(15, 0); 1 further point
  constraints: 8 end point, 7 point on line, 4 perpendicular
extrude "Extrusion70" cut sketch "Sketch70" distance "d169" = 2; taper "d170" = 0 deg
sketch "Sketch71"
  geometry: L1 (-29.5, 19)-(-29.5, 3) reference; L2 (-121, 0)-(0, 0) reference; L3 (0, 0)-(0, 22) reference; L4 (-121, 22)-(-121, 19) reference; L5 (0, 15)-(-29.5, 15); L6 (-29.5, 3)-(-29.5, 0); L7 (-15, 15)-(-15, 0); L8 (-4, 15)-(-4, 0); 1 further point
  constraints: 8 end point, 7 point on line, 4 perpendicular
extrude "Extrusion71" cut sketch "Sketch71" distance "d171" = 2; taper "d172" = 0 deg
sketch "Sketch72"
  geometry: L1 (0, 4)-(0, 0) reference; L2 (0, 4)-(-29.25, 4) reference; L3 (-29.25, 0)-(-29.25, 4) reference; L4 (0, 1)-(-29.25, 1); 1 further point
  constraints: 2 end point, 2 point on line, 1 perpendicular
extrude "Extrusion72" join sketch "Sketch72" distance "d173" = 0.5; taper "d174" = 0 deg
sketch "Sketch73"
  geometry: L1 (0, 0)-(0, 4) reference; L2 (29.25, 4)-(29.25, 0) reference; L3 (0, 4)-(29.25, 4) reference; L4 (29.25, 1)-(0, 1); 1 further point
  constraints: 2 end point, 2 point on line, 1 parallel
extrude "Extrusion73" join sketch "Sketch73" distance "d175" = 0.5; taper "d176" = 0 deg
chamfer "Chamfer9" distance "d177" = 3; stored, may be unused: second distance "d178" = 4, angle "d179" = 45 deg
chamfer "Chamfer10" distance "d180" = 1; stored, may be unused: second distance "d181" = 4, angle "d182" = 45 deg
chamfer "Chamfer11" distance "d183" = 1; stored, may be unused: second distance "d184" = 4, angle "d185" = 45 deg
chamfer "Chamfer12" distance "d186" = 1; stored, may be unused: second distance "d187" = 4, angle "d188" = 45 deg
chamfer "Chamfer13" distance "d189" = 2; stored, may be unused: second distance "d190" = 4, angle "d191" = 45 deg
chamfer "Chamfer14" distance "d192" = 0.5; stored, may be unused: second distance "d193" = 4, angle "d194" = 45 deg
chamfer "Chamfer15" distance "d195" = 14.25; stored, may be unused: second distance "d196" = 4, angle "d197" = 45 deg
chamfer "Chamfer16" distance "d198" = 3; stored, may be unused: second distance "d199" = 4, angle "d200" = 45 deg
body "Solid1"
